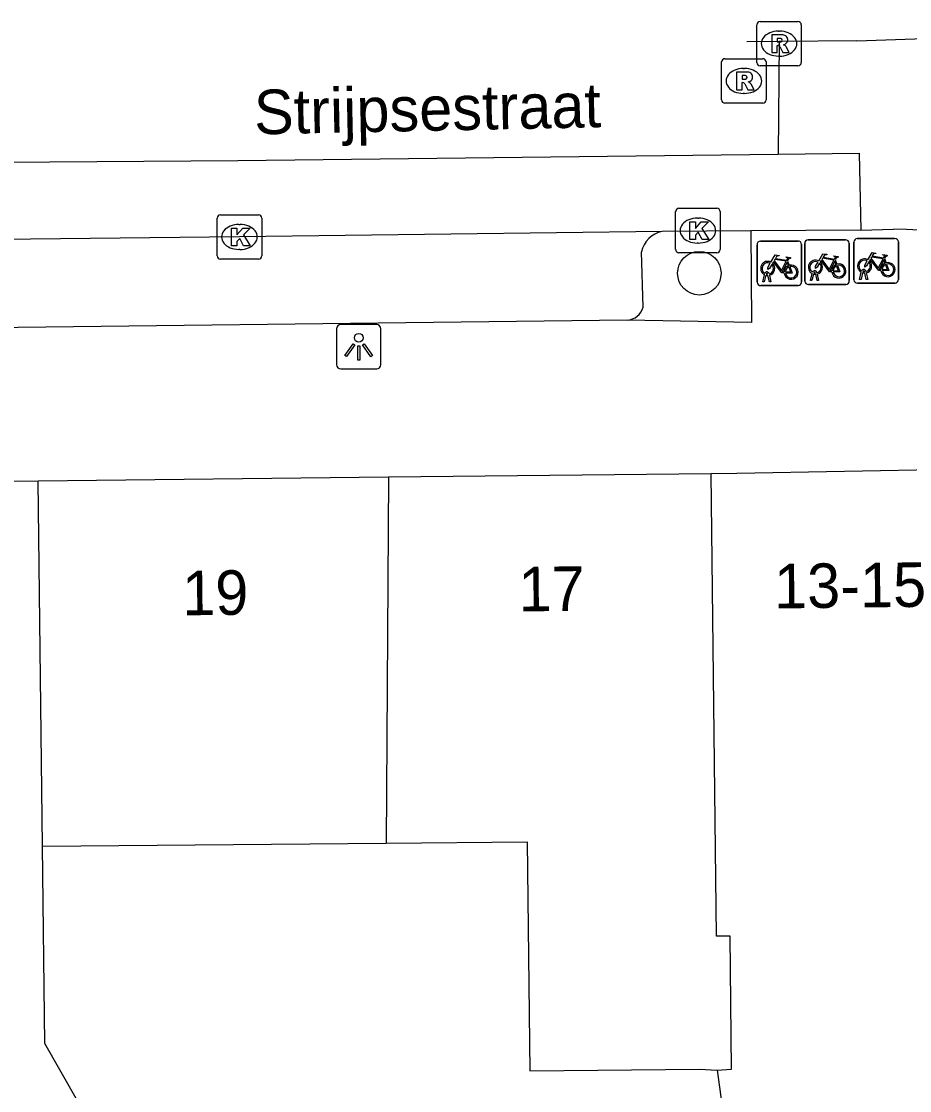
# Model space of a CAD drawing. Extents: x 159961 to 160856, y 382704 to 383353.
# Drawn here: x 160130.02 to 160150, y 383270.29 to 383294.32 of the extents above; entities that cross this region are included whole.
import ezdxf

# ---------------------------------------------------------------- set-up
doc = ezdxf.new("R2010")
doc.units = 0
for name, color, linetype in [('IMGEO_Boom', 7, 'Continuous'), ('IMGEO_Fietsenrek', 7, 'Continuous'), ('IMGEO_Kolk', 7, 'Continuous'), ('IMGEO_Lichtpunt', 7, 'Continuous'), ('IMGEO_Openbare_ruimte_label', 7, 'Continuous'), ('IMGEO_Pand', 7, 'Continuous'), ('IMGEO_Pand_nummerreeks', 7, 'Continuous'), ('IMGEO_Parkeervlak_open', 7, 'Continuous'), ('IMGEO_Rijbaan_lokaal_gesloten', 7, 'Continuous'), ('IMGEO_Rijbaan_lokaal_open', 7, 'Continuous'), ('IMGEO_Rioolput', 7, 'Continuous'), ('IMGEO_Voetpad_open', 7, 'Continuous')]:
    doc.layers.add(name, color=color, linetype=linetype)

msp = doc.modelspace()

# ---------------------------------------------------------------- linework, layer by layer
at = {"layer": 'IMGEO_Boom'}
msp.add_circle((160145.271, 383288.663), 0.489, dxfattribs=at)
at = {"layer": 'IMGEO_Fietsenrek'}
for p, q in [((160147.718, 383289.413), (160148.559, 383289.413)), ((160148.559, 383289.413), (160147.718, 383289.413)), ((160148.823, 383289.442), (160149.664, 383289.442)), ((160149.664, 383289.442), (160148.823, 383289.442)), ((160146.57, 383288.462), (160146.57, 383289.303)), ((160146.57, 383289.303), (160146.57, 383288.462)), ((160146.645, 383289.387), (160147.486, 383289.387)), ((160147.486, 383289.387), (160146.645, 383289.387)), ((160147.57, 383289.312), (160147.57, 383288.471)), ((160147.57, 383288.471), (160147.57, 383289.312)), ((160147.643, 383288.488), (160147.643, 383289.329)), ((160147.643, 383289.329), (160147.643, 383288.488)), ((160148.643, 383289.338), (160148.643, 383288.497)), ((160148.643, 383288.497), (160148.643, 383289.338)), ((160148.748, 383288.517), (160148.748, 383289.358)), ((160148.748, 383289.358), (160148.748, 383288.517)), ((160149.748, 383289.367), (160149.748, 383288.526)), ((160149.748, 383288.526), (160149.748, 383289.367)), ((160147.257, 383288.936), (160147.293, 383288.841)), ((160148.33, 383288.962), (160148.366, 383288.867)), ((160149.435, 383288.991), (160149.471, 383288.896)), ((160147.881, 383288.669), (160147.88, 383288.673)), ((160147.912, 383288.68), (160147.913, 383288.673)), ((160148.875, 383288.526), (160148.914, 383288.686)), ((160148.944, 383288.674), (160148.909, 383288.526)), ((160148.986, 383288.698), (160148.985, 383288.702)), ((160149.027, 383288.526), (160148.993, 383288.668)), ((160149.017, 383288.709), (160149.018, 383288.702)), ((160149.025, 383288.672), (160149.06, 383288.526)), ((160146.697, 383288.471), (160146.736, 383288.631)), ((160146.731, 383288.471), (160146.697, 383288.471)), ((160146.766, 383288.619), (160146.731, 383288.471)), ((160146.808, 383288.643), (160146.807, 383288.647)), ((160146.849, 383288.471), (160146.815, 383288.613)), ((160146.839, 383288.654), (160146.84, 383288.647)), ((160146.847, 383288.617), (160146.882, 383288.471)), ((160146.882, 383288.471), (160146.849, 383288.471)), ((160147.77, 383288.497), (160147.809, 383288.657)), ((160147.804, 383288.497), (160147.77, 383288.497)), ((160147.839, 383288.645), (160147.804, 383288.497)), ((160147.922, 383288.497), (160147.888, 383288.639)), ((160147.92, 383288.643), (160147.955, 383288.497)), ((160147.955, 383288.497), (160147.922, 383288.497)), ((160149.673, 383288.442), (160148.832, 383288.442)), ((160148.832, 383288.442), (160149.673, 383288.442)), ((160148.909, 383288.526), (160148.875, 383288.526)), ((160149.06, 383288.526), (160149.027, 383288.526)), ((160147.495, 383288.387), (160146.654, 383288.387)), ((160146.654, 383288.387), (160147.495, 383288.387)), ((160148.568, 383288.413), (160147.727, 383288.413)), ((160147.727, 383288.413), (160148.568, 383288.413))]:
    msp.add_line(p, q, dxfattribs=at)
for points in [[(160146.883, 383288.913), (160146.978, 383289.077), (160147.064, 383289.063), (160147.066, 383289.054), (160147.01, 383289.043), (160146.983, 383288.998), (160147.239, 383288.957)], [(160147.179, 383288.669), (160147.129, 383288.669), (160146.938, 383288.92), (160146.919, 383288.888)], [(160147.226, 383288.932), (160146.969, 383288.973), (160146.952, 383288.944), (160147.119, 383288.724), (160147.226, 383288.932)], [(160147.274, 383288.834), (160147.244, 383288.911), (160147.135, 383288.693), (160147.178, 383288.693)], [(160147.239, 383288.957), (160147.264, 383289.006), (160147.258, 383289.01), (160147.235, 383289.014), (160147.223, 383289.021), (160147.222, 383289.024), (160147.224, 383289.029), (160147.319, 383289.014), (160147.321, 383289.004), (160147.311, 383288.991), (160147.299, 383288.985), (160147.285, 383288.991), (160147.257, 383288.936)], [(160147.977, 383288.887), (160147.925, 383288.797), (160147.885, 383288.771), (160147.886, 383288.819), (160147.941, 383288.913)], [(160147.956, 383288.939), (160148.051, 383289.103), (160148.137, 383289.089), (160148.139, 383289.08), (160148.083, 383289.069), (160148.056, 383289.024), (160148.312, 383288.983)], [(160148.252, 383288.695), (160148.202, 383288.695), (160148.011, 383288.946), (160147.992, 383288.914)], [(160148.299, 383288.958), (160148.042, 383288.999), (160148.025, 383288.97), (160148.192, 383288.75), (160148.299, 383288.958)], [(160148.347, 383288.86), (160148.317, 383288.937), (160148.208, 383288.719), (160148.251, 383288.719)], [(160148.312, 383288.983), (160148.337, 383289.032), (160148.331, 383289.036), (160148.308, 383289.04), (160148.296, 383289.047), (160148.295, 383289.05), (160148.297, 383289.055), (160148.392, 383289.04), (160148.394, 383289.03), (160148.384, 383289.017), (160148.372, 383289.011), (160148.358, 383289.017), (160148.33, 383288.962)], [(160149.082, 383288.916), (160149.03, 383288.826), (160148.99, 383288.801), (160148.991, 383288.848), (160149.046, 383288.942)], [(160149.061, 383288.968), (160149.156, 383289.132), (160149.242, 383289.118), (160149.244, 383289.109), (160149.188, 383289.098), (160149.161, 383289.053), (160149.417, 383289.012)], [(160149.357, 383288.724), (160149.307, 383288.724), (160149.116, 383288.975), (160149.097, 383288.943)], [(160149.404, 383288.987), (160149.147, 383289.028), (160149.13, 383288.999), (160149.297, 383288.779), (160149.404, 383288.987)], [(160149.452, 383288.889), (160149.422, 383288.966), (160149.313, 383288.748), (160149.356, 383288.748)], [(160149.417, 383289.012), (160149.442, 383289.061), (160149.436, 383289.065), (160149.413, 383289.069), (160149.401, 383289.076), (160149.4, 383289.079), (160149.402, 383289.084), (160149.497, 383289.069), (160149.499, 383289.059), (160149.489, 383289.046), (160149.477, 383289.04), (160149.463, 383289.046), (160149.435, 383288.991)], [(160146.904, 383288.861), (160146.852, 383288.771), (160146.812, 383288.746), (160146.813, 383288.793), (160146.868, 383288.887)], [(160147.208, 383288.693), (160147.328, 383288.692), (160147.284, 383288.806)], [(160147.304, 383288.813), (160147.359, 383288.668), (160147.209, 383288.668)], [(160148.281, 383288.719), (160148.401, 383288.718), (160148.357, 383288.832)], [(160148.377, 383288.839), (160148.432, 383288.694), (160148.282, 383288.694)], [(160149.386, 383288.748), (160149.506, 383288.747), (160149.462, 383288.861)], [(160149.482, 383288.868), (160149.537, 383288.723), (160149.387, 383288.723)]]:
    msp.add_lwpolyline(points, dxfattribs=at)
for centre, radius, start, end in [((160147.721, 383289.335), 0.0779, 92.4484, 184.2845), ((160147.721, 383289.335), 0.0779, 92.4484, 184.2845), ((160148.565, 383289.335), 0.0779, 2.4484, 94.2845), ((160148.565, 383289.335), 0.0779, 2.4484, 94.2845), ((160148.826, 383289.364), 0.0779, 92.4484, 184.2845), ((160148.826, 383289.364), 0.0779, 92.4484, 184.2845), ((160149.67, 383289.364), 0.0779, 2.4484, 94.2845), ((160149.67, 383289.364), 0.0779, 2.4484, 94.2845), ((160146.648, 383289.309), 0.0779, 92.4484, 184.2845), ((160146.648, 383289.309), 0.0779, 92.4484, 184.2845), ((160147.492, 383289.309), 0.0779, 2.4484, 94.2845), ((160147.492, 383289.309), 0.0779, 2.4484, 94.2845), ((160146.81, 383288.772), 0.159, 62.6766, 242.1369), ((160147.883, 383288.798), 0.159, 62.6766, 242.1369), ((160147.883, 383288.798), 0.129, 63.3192, 238.903), ((160147.883, 383288.798), 0.159, 283.5766, 46.6042), ((160148.988, 383288.827), 0.159, 62.6766, 242.1369), ((160148.988, 383288.827), 0.129, 63.3192, 238.903), ((160148.988, 383288.827), 0.129, 283.6043, 43.4302), ((160148.988, 383288.827), 0.159, 283.5766, 46.6042), ((160146.81, 383288.772), 0.129, 63.3192, 238.903), ((160146.79, 383288.643), 0.0499, 12.8025, 158.6934), ((160146.81, 383288.772), 0.129, 283.6043, 43.4302), ((160146.81, 383288.772), 0.159, 283.5766, 46.6042), ((160147.337, 383288.688), 0.159, 113.3408, 178.3217), ((160147.337, 383288.688), 0.159, 187.0065, 105.7708), ((160147.337, 383288.688), 0.129, 113.923, 177.9556), ((160147.337, 383288.688), 0.129, 188.6715, 104.5883), ((160147.863, 383288.669), 0.0499, 12.8025, 158.6934), ((160147.863, 383288.669), 0.0174, 12.8025, 163.4502), ((160147.883, 383288.798), 0.129, 253.415, 269.0204), ((160147.883, 383288.798), 0.129, 283.6043, 43.4302), ((160148.41, 383288.714), 0.159, 113.3408, 178.3217), ((160148.41, 383288.714), 0.159, 187.0065, 105.7708), ((160148.41, 383288.714), 0.129, 113.923, 177.9556), ((160148.41, 383288.714), 0.129, 188.6715, 104.5883), ((160148.968, 383288.698), 0.0499, 12.8025, 158.6934), ((160148.988, 383288.827), 0.159, 253.9967, 271.7867), ((160148.968, 383288.698), 0.0174, 12.8025, 163.4502), ((160148.988, 383288.827), 0.129, 253.415, 269.0204), ((160149.515, 383288.743), 0.159, 113.3408, 178.3217), ((160149.515, 383288.743), 0.159, 187.0065, 105.7708), ((160149.515, 383288.743), 0.129, 113.923, 177.9556), ((160149.515, 383288.743), 0.129, 188.6715, 104.5883), ((160146.648, 383288.465), 0.0779, 182.4484, 274.2845), ((160146.648, 383288.465), 0.0779, 182.4484, 274.2845), ((160146.81, 383288.772), 0.159, 253.9967, 271.7867), ((160146.79, 383288.643), 0.0174, 12.8025, 163.4502), ((160146.81, 383288.772), 0.129, 253.415, 269.0204), ((160147.492, 383288.465), 0.0779, 272.4484, 4.2845), ((160147.492, 383288.465), 0.0779, 272.4484, 4.2845), ((160147.721, 383288.491), 0.0779, 182.4484, 274.2845), ((160147.721, 383288.491), 0.0779, 182.4484, 274.2845), ((160147.883, 383288.798), 0.159, 253.9967, 271.7867), ((160148.565, 383288.491), 0.0779, 272.4484, 4.2845), ((160148.565, 383288.491), 0.0779, 272.4484, 4.2845), ((160148.826, 383288.52), 0.0779, 182.4484, 274.2845), ((160148.826, 383288.52), 0.0779, 182.4484, 274.2845), ((160149.67, 383288.52), 0.0779, 272.4484, 4.2845), ((160149.67, 383288.52), 0.0779, 272.4484, 4.2845)]:
    msp.add_arc(centre, radius, start, end, dxfattribs=at)
at = {"layer": 'IMGEO_Kolk'}
for p, q in [((160144.814, 383290.122), (160145.666, 383290.122)), ((160134.428, 383289.052), (160134.428, 383289.904)), ((160134.503, 383289.978), (160135.355, 383289.978)), ((160135.429, 383289.904), (160135.429, 383289.052)), ((160144.739, 383289.196), (160144.739, 383290.048)), ((160145.227, 383289.902), (160145.252, 383289.902)), ((160145.74, 383290.048), (160145.74, 383289.196)), ((160134.916, 383289.758), (160134.941, 383289.758)), ((160134.939, 383289.198), (160134.914, 383289.198)), ((160145.25, 383289.342), (160145.225, 383289.342)), ((160135.355, 383288.978), (160134.503, 383288.978)), ((160145.666, 383289.122), (160144.814, 383289.122))]:
    msp.add_line(p, q, dxfattribs=at)
for points in [[(160144.814, 383290.122), (160145.666, 383290.122)], [(160134.428, 383289.052), (160134.428, 383289.904)], [(160134.503, 383289.978), (160135.355, 383289.978)], [(160135.429, 383289.904), (160135.429, 383289.052)], [(160144.739, 383289.196), (160144.739, 383290.048)], [(160145.74, 383290.048), (160145.74, 383289.196)], [(160134.749, 383289.678), (160134.872, 383289.678), (160134.872, 383289.527), (160135.002, 383289.678), (160135.166, 383289.678), (160135.02, 383289.527), (160135.173, 383289.278), (160135.021, 383289.278), (160134.936, 383289.442), (160134.872, 383289.375), (160134.872, 383289.278), (160134.749, 383289.278), (160134.749, 383289.678)], [(160145.06, 383289.822), (160145.183, 383289.822), (160145.183, 383289.671), (160145.313, 383289.822), (160145.477, 383289.822), (160145.331, 383289.671), (160145.484, 383289.422), (160145.332, 383289.422), (160145.247, 383289.586), (160145.183, 383289.519), (160145.183, 383289.422), (160145.06, 383289.422), (160145.06, 383289.822)], [(160135.355, 383288.978), (160134.503, 383288.978)], [(160145.666, 383289.122), (160144.814, 383289.122)]]:
    msp.add_lwpolyline(points, dxfattribs=at)
for centre, start, end in [((160144.816, 383290.046), 91.552, 178.448), ((160144.816, 383290.046), 91.552, 178.448), ((160145.664, 383290.046), 1.552, 88.448), ((160145.664, 383290.046), 1.552, 88.448), ((160134.505, 383289.902), 91.552, 178.448), ((160134.505, 383289.902), 91.552, 178.448), ((160135.353, 383289.902), 1.552, 88.448), ((160135.353, 383289.902), 1.552, 88.448), ((160144.816, 383289.198), 181.552, 268.448), ((160144.816, 383289.198), 181.552, 268.448), ((160145.664, 383289.198), 271.552, 358.448), ((160145.664, 383289.198), 271.552, 358.448), ((160134.505, 383289.054), 181.552, 268.448), ((160134.505, 383289.054), 181.552, 268.448), ((160135.353, 383289.054), 271.552, 358.448), ((160135.353, 383289.054), 271.552, 358.448)]:
    msp.add_arc(centre, 0.0765, start, end, dxfattribs=at)
for centre, major_axis, ratio, start_param, end_param in [((160145.226, 383289.622), (-0.387, 0.002), 0.722429, 4.712389, 7.853982), ((160145.251, 383289.622), (-0.39, 0.002), 0.717154, 1.570796, 4.712389), ((160134.915, 383289.478), (-0.387, 0.002), 0.722429, 4.712389, 7.853982), ((160134.94, 383289.478), (-0.39, 0.002), 0.717154, 1.570796, 4.712389)]:
    msp.add_ellipse(centre, major_axis=major_axis, ratio=ratio, start_param=start_param, end_param=end_param, dxfattribs=at)
at = {"layer": 'IMGEO_Lichtpunt'}
for p, q in [((160138.015, 383287.51), (160137.207, 383287.51)), ((160138.015, 383287.51), (160137.207, 383287.51)), ((160137.113, 383287.415), (160137.113, 383286.608)), ((160137.113, 383287.415), (160137.113, 383286.608)), ((160138.109, 383286.608), (160138.109, 383287.415)), ((160138.109, 383286.608), (160138.109, 383287.415)), ((160137.207, 383286.514), (160138.015, 383286.514)), ((160137.207, 383286.514), (160138.015, 383286.514))]:
    msp.add_line(p, q, dxfattribs=at)
for points in [[(160137.487, 383287.079), (160137.526, 383287.051), (160137.338, 383286.789), (160137.3, 383286.816), (160137.487, 383287.079)], [(160137.589, 383287.031), (160137.636, 383287.031), (160137.636, 383286.709), (160137.589, 383286.709), (160137.589, 383287.031)], [(160137.699, 383287.051), (160137.737, 383287.078), (160137.924, 383286.816), (160137.885, 383286.788), (160137.699, 383287.051)]]:
    msp.add_lwpolyline(points, dxfattribs=at)
msp.add_circle((160137.612, 383287.213), 0.0994, dxfattribs=at)
for centre, start, end in [((160137.207, 383287.415), 90, 180), ((160137.207, 383287.415), 90, 180), ((160138.015, 383287.415), 0, 90), ((160138.015, 383287.415), 0, 90), ((160137.207, 383286.608), 180, 270), ((160137.207, 383286.608), 180, 270), ((160138.015, 383286.608), 270, 0), ((160138.015, 383286.608), 270, 360)]:
    msp.add_arc(centre, 0.0946, start, end, dxfattribs=at)
at = {"layer": 'IMGEO_Pand'}
for points in [[(160145.534, 383284.157), (160138.282, 383284.079)], [(160153.377, 383284.295), (160146.117, 383284.164), (160145.534, 383284.157)], [(160145.673, 383270.75), (160145.997, 383270.772), (160145.964, 383273.767), (160145.656, 383273.765), (160145.534, 383284.157)], [(160130.404, 383283.994), (160124.94, 383283.935), (160123.651, 383283.915)], [(160138.282, 383284.079), (160130.404, 383283.994)], [(160130.5, 383275.79), (160130.404, 383283.994)], [(160138.282, 383284.079), (160138.231, 383275.857)], [(160127.588, 383264.881), (160130.029, 383260.62), (160134.089, 383262.933), (160130.674, 383268.928), (160131.626, 383269.47), (160130.551, 383271.356), (160130.5, 383275.79)], [(160130.5, 383275.79), (160138.231, 383275.857)], [(160138.231, 383275.857), (160141.398, 383275.884), (160141.458, 383270.735), (160145.276, 383270.779), (160145.673, 383270.75)], [(160145.673, 383270.75), (160146.176, 383267.1), (160146.182, 383266.849), (160146.233, 383263.133)]]:
    msp.add_lwpolyline(points, dxfattribs=at)
at = {"layer": 'IMGEO_Parkeervlak_open'}
msp.add_lwpolyline([(160144.007, 383287.9), (160143.974, 383289.141)], dxfattribs=at)
for centre, radius, start, end in [((160144.541, 383289.035), 0.577, 100.8145, 169.4346), ((160143.639, 383287.99), 0.379, 271.5182, 346.3071)]:
    msp.add_arc(centre, radius, start, end, dxfattribs=at)
at = {"layer": 'IMGEO_Rijbaan_lokaal_gesloten'}
for points in [[(160147.064, 383293.87), (160146.343, 383293.862)], [(160080.248, 383290.596), (160083.482, 383290.631), (160098.541, 383290.818), (160124.31, 383291.125), (160134.891, 383291.195), (160147.047, 383291.339)], [(160148.904, 383289.629), (160146.428, 383289.619)], [(160144.433, 383289.602), (160134.929, 383289.478), (160125.519, 383289.373)], [(160146.428, 383289.619), (160144.433, 383289.602)]]:
    msp.add_lwpolyline(points, dxfattribs=at)
at = {"layer": 'IMGEO_Rijbaan_lokaal_open'}
for points in [[(160147.064, 383293.87), (160147.047, 383291.339)], [(160148.817, 383293.89), (160147.064, 383293.87)], [(160147.047, 383291.339), (160148.864, 383291.361), (160148.904, 383289.629)], [(160148.904, 383289.629), (160149.637, 383289.651)]]:
    msp.add_lwpolyline(points, dxfattribs=at)
for centre, radius, start, end in [((160134.74, 383748.201), 454.529, 271.77471, 272.6478), ((160149.741, 383283.92), 5.732, 2.1108, 91.0379)]:
    msp.add_arc(centre, radius, start, end, dxfattribs=at)
at = {"layer": 'IMGEO_Rioolput'}
for p, q in [((160146.563, 383293.397), (160146.563, 383294.249)), ((160146.638, 383294.323), (160147.49, 383294.323)), ((160147.564, 383294.249), (160147.564, 383293.397)), ((160147.051, 383294.103), (160147.076, 383294.103)), ((160145.848, 383293.485), (160146.7, 383293.485)), ((160147.074, 383293.543), (160147.049, 383293.543)), ((160145.773, 383292.559), (160145.773, 383293.411)), ((160146.261, 383293.265), (160146.286, 383293.265)), ((160147.49, 383293.323), (160146.638, 383293.323)), ((160146.774, 383293.411), (160146.774, 383292.559)), ((160146.284, 383292.705), (160146.259, 383292.705)), ((160146.7, 383292.485), (160145.848, 383292.485))]:
    msp.add_line(p, q, dxfattribs=at)
for points in [[(160146.563, 383293.397), (160146.563, 383294.249)], [(160146.638, 383294.323), (160147.49, 383294.323)], [(160147.564, 383294.249), (160147.564, 383293.397)], [(160147.152, 383294.021), (160146.9, 383294.023), (160146.9, 383293.623)], [(160146.9, 383293.623), (160147.024, 383293.623), (160147.024, 383293.785), (160147.035, 383293.785)], [(160147.078, 383293.942), (160147.024, 383293.942), (160147.024, 383293.861)], [(160147.024, 383293.861), (160147.076, 383293.861)], [(160147.082, 383293.756), (160147.153, 383293.623), (160147.293, 383293.623), (160147.228, 383293.749)], [(160145.848, 383293.485), (160146.7, 383293.485)], [(160145.773, 383292.559), (160145.773, 383293.411)], [(160147.49, 383293.323), (160146.638, 383293.323)], [(160146.774, 383293.411), (160146.774, 383292.559)], [(160146.362, 383293.183), (160146.11, 383293.185), (160146.11, 383292.785)], [(160146.288, 383293.104), (160146.234, 383293.104), (160146.234, 383293.023)], [(160146.234, 383293.023), (160146.286, 383293.023)], [(160146.11, 383292.785), (160146.234, 383292.785), (160146.234, 383292.947), (160146.245, 383292.947)], [(160146.292, 383292.918), (160146.363, 383292.785), (160146.503, 383292.785), (160146.438, 383292.911)], [(160146.7, 383292.485), (160145.848, 383292.485)]]:
    msp.add_lwpolyline(points, dxfattribs=at)
for centre, radius, start, end in [((160146.64, 383294.247), 0.0765, 91.552, 178.448), ((160146.64, 383294.247), 0.0765, 91.552, 178.448), ((160147.488, 383294.247), 0.0765, 1.552, 88.448), ((160147.488, 383294.247), 0.0765, 1.552, 88.448), ((160147.151, 383293.911), 0.109, 350.3612, 89.416), ((160147.034, 383293.732), 0.0533, 26.0293, 88.6989), ((160147.06, 383294.05), 0.19, 274.7715, 282.9687), ((160147.084, 383293.846), 0.0964, 77.0061, 93.1865), ((160147.098, 383293.903), 0.0378, 276.6634, 79.6772), ((160147.149, 383293.911), 0.112, 277.5842, 350.9817), ((160147.133, 383293.696), 0.108, 29.5134, 73.7905), ((160145.85, 383293.409), 0.0765, 91.552, 178.448), ((160145.85, 383293.409), 0.0765, 91.552, 178.448), ((160146.698, 383293.409), 0.0765, 1.552, 88.448), ((160146.698, 383293.409), 0.0765, 1.552, 88.448), ((160146.64, 383293.399), 0.0765, 181.552, 268.448), ((160146.64, 383293.399), 0.0765, 181.552, 268.448), ((160147.488, 383293.399), 0.0765, 271.552, 358.448), ((160147.488, 383293.399), 0.0765, 271.552, 358.448), ((160146.27, 383293.212), 0.19, 274.7715, 282.9687), ((160146.294, 383293.008), 0.0964, 77.0061, 93.1865), ((160146.308, 383293.065), 0.0378, 276.6634, 79.6772), ((160146.361, 383293.073), 0.109, 350.3612, 89.416), ((160146.359, 383293.073), 0.112, 277.5842, 350.9817), ((160146.244, 383292.894), 0.0533, 26.0293, 88.6989), ((160146.343, 383292.858), 0.108, 29.5134, 73.7905), ((160145.85, 383292.561), 0.0765, 181.552, 268.448), ((160145.85, 383292.561), 0.0765, 181.552, 268.448), ((160146.698, 383292.561), 0.0765, 271.552, 358.448), ((160146.698, 383292.561), 0.0765, 271.552, 358.448)]:
    msp.add_arc(centre, radius, start, end, dxfattribs=at)
for centre, major_axis, ratio, start_param, end_param in [((160147.05, 383293.823), (-0.387, 0.002), 0.722429, 4.712389, 7.853982), ((160147.075, 383293.823), (-0.39, 0.002), 0.717154, 1.570796, 4.712389), ((160146.26, 383292.985), (-0.387, 0.002), 0.722429, 4.712389, 7.853982), ((160146.285, 383292.985), (-0.39, 0.002), 0.717154, 1.570796, 4.712389)]:
    msp.add_ellipse(centre, major_axis=major_axis, ratio=ratio, start_param=start_param, end_param=end_param, dxfattribs=at)
at = {"layer": 'IMGEO_Voetpad_open'}
for points in [[(160146.428, 383289.619), (160146.441, 383287.558), (160143.649, 383287.611)], [(160143.649, 383287.611), (160126.21, 383287.402)]]:
    msp.add_lwpolyline(points, dxfattribs=at)

# ---------------------------------------------------------------- texts
at = {"layer": 'IMGEO_Openbare_ruimte_label'}
msp.add_text('Strijpsestraat', height=1, rotation=1.203, dxfattribs=at).set_placement((160135.266, 383291.782))
at = {"layer": 'IMGEO_Pand_nummerreeks'}
for s, p in [('19', (160133.646, 383280.974)), ('17', (160141.211, 383281.062)), ('13-15', (160146.957, 383281.129))]:
    msp.add_text(s, height=1, rotation=0.6646, dxfattribs=at).set_placement(p)

doc.saveas('drawing.dxf')
